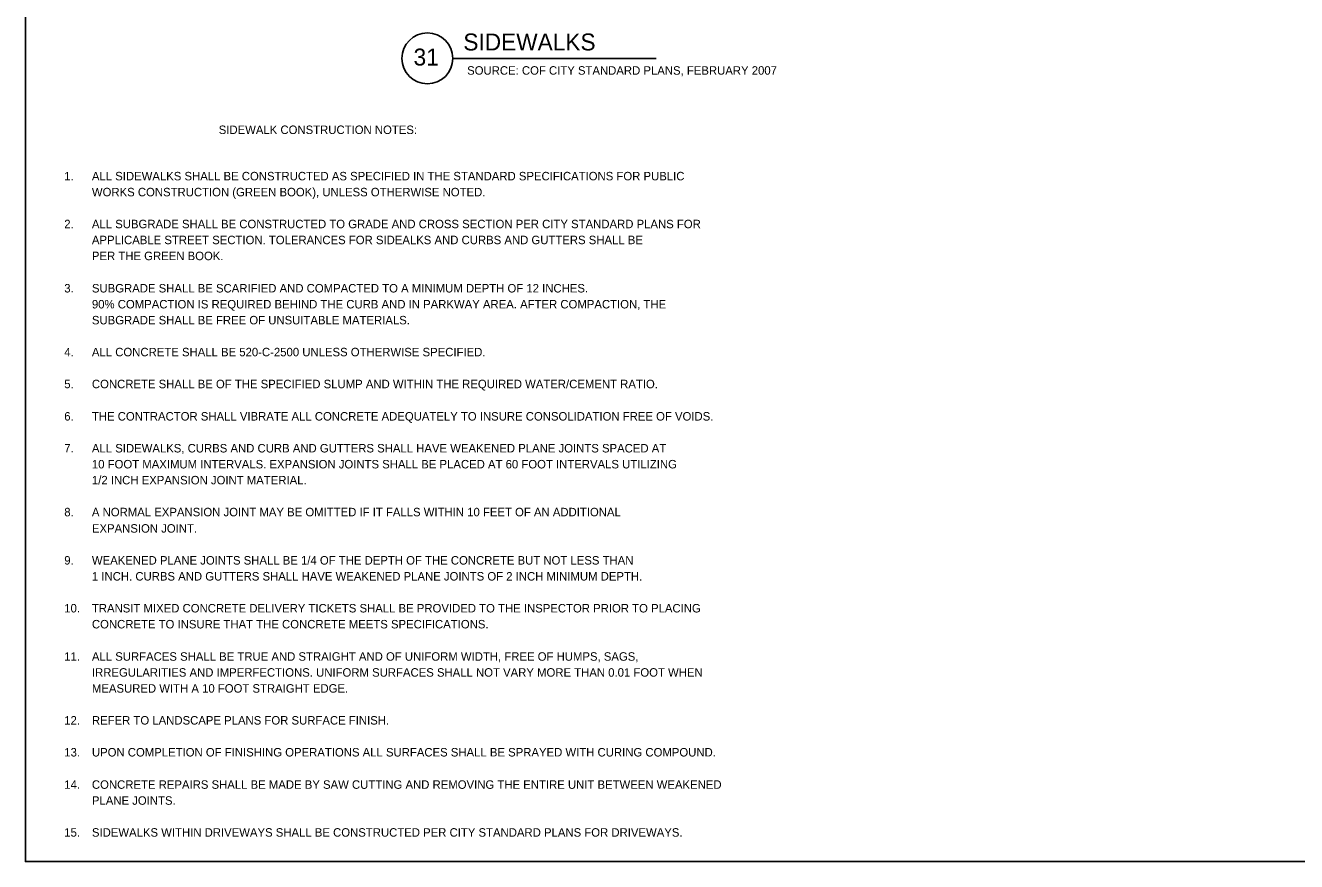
# Model space of a CAD drawing. Extents: x -118779 to -116979, y -104389 to -102939.
# Drawn here: x -118779 to -117879, y -104389 to -103797 of the extents above; entities that cross this region are included whole.
import ezdxf

# ---------------------------------------------------------------- set-up
doc = ezdxf.new("R2010")
doc.units = 0
for name, color, linetype in [('Default', 7, 'Continuous'), ('Misc CnstDet(22)', 7, 'Continuous'), ('Nongeo Data(60)', 7, 'Continuous')]:
    doc.layers.add(name, color=color, linetype=linetype)

msp = doc.modelspace()

# ---------------------------------------------------------------- linework, layer by layer
at = {"layer": 'Default'}
msp.add_lwpolyline([(-118779.39, -102939.25), (-116979.39, -102939.25), (-116979.39, -104389.25), (-118779.39, -104389.25)], close=True, dxfattribs=at)
at = {"layer": 'Nongeo Data(60)'}
msp.add_line((-118476.78, -103820.62), (-118332.78, -103820.62), dxfattribs=at)
msp.add_circle((-118494.78, -103820.62), 18, dxfattribs=at)

# ---------------------------------------------------------------- texts
at = {"layer": 'Misc CnstDet(22)'}
for s, height, p in [('SIDEWALKS', 12, (-118469.33, -103815.02)), ('31', 12, (-118504.57, -103825.69)), ('SOURCE: COF CITY STANDARD PLANS, FEBRUARY 2007', 6, (-118466.65, -103832.18)), ('SIDEWALK CONSTRUCTION NOTES:', 6, (-118642.52, -103874.18)), ('1.', 6, (-118751.88, -103906.99)), ('ALL SIDEWALKS SHALL BE CONSTRUCTED AS SPECIFIED IN THE STANDARD SPECIFICATIONS FOR PUBLIC', 6, (-118732.31, -103906.99)), ('WORKS CONSTRUCTION (GREEN BOOK), UNLESS OTHERWISE NOTED.', 6, (-118732.31, -103918.29)), ('2.', 6, (-118751.88, -103940.88)), ('ALL SUBGRADE SHALL BE CONSTRUCTED TO GRADE AND CROSS SECTION PER CITY STANDARD PLANS FOR', 6, (-118732.31, -103940.88)), ('APPLICABLE STREET SECTION. TOLERANCES FOR SIDEALKS AND CURBS AND GUTTERS SHALL BE', 6, (-118732.31, -103952.18)), ('PER THE GREEN BOOK.', 6, (-118732.31, -103963.48)), ('3.', 6, (-118751.88, -103986.36)), ('SUBGRADE SHALL BE SCARIFIED AND COMPACTED TO A MINIMUM DEPTH OF 12 INCHES.', 6, (-118732.31, -103986.36)), ('90% COMPACTION IS REQUIRED BEHIND THE CURB AND IN PARKWAY AREA. AFTER COMPACTION, THE', 6, (-118732.31, -103997.66)), ('SUBGRADE SHALL BE FREE OF UNSUITABLE MATERIALS.', 6, (-118732.31, -104008.95)), ('4.', 6, (-118751.88, -104031.55)), ('ALL CONCRETE SHALL BE 520-C-2500 UNLESS OTHERWISE SPECIFIED.', 6, (-118732.31, -104031.55)), ('5.', 6, (-118751.88, -104054.15)), ('CONCRETE SHALL BE OF THE SPECIFIED SLUMP AND WITHIN THE REQUIRED WATER/CEMENT RATIO.', 6, (-118732.31, -104054.15)), ('6.', 6, (-118751.88, -104077.03)), ('THE CONTRACTOR SHALL VIBRATE ALL CONCRETE ADEQUATELY TO INSURE CONSOLIDATION FREE OF VOIDS.', 6, (-118732.31, -104077.03)), ('7.', 6, (-118751.88, -104099.62)), ('ALL SIDEWALKS, CURBS AND CURB AND GUTTERS SHALL HAVE WEAKENED PLANE JOINTS SPACED AT', 6, (-118732.31, -104099.62)), ('10 FOOT MAXIMUM INTERVALS. EXPANSION JOINTS SHALL BE PLACED AT 60 FOOT INTERVALS UTILIZING', 6, (-118732.31, -104110.92)), ('1/2 INCH EXPANSION JOINT MATERIAL.', 6, (-118732.31, -104122.22)), ('8.', 6, (-118751.88, -104144.82)), ('A NORMAL EXPANSION JOINT MAY BE OMITTED IF IT FALLS WITHIN 10 FEET OF AN ADDITIONAL', 6, (-118732.31, -104144.82)), ('EXPANSION JOINT.', 6, (-118732.31, -104156.4)), ('9.', 6, (-118751.88, -104178.99)), ('WEAKENED PLANE JOINTS SHALL BE 1/4 OF THE DEPTH OF THE CONCRETE BUT NOT LESS THAN', 6, (-118732.31, -104178.99)), ('1 INCH. CURBS AND GUTTERS SHALL HAVE WEAKENED PLANE JOINTS OF 2 INCH MINIMUM DEPTH.', 6, (-118732.31, -104190.29)), ('10.', 6, (-118751.88, -104212.89)), ('TRANSIT MIXED CONCRETE DELIVERY TICKETS SHALL BE PROVIDED TO THE INSPECTOR PRIOR TO PLACING', 6, (-118732.31, -104212.89)), ('CONCRETE TO INSURE THAT THE CONCRETE MEETS SPECIFICATIONS.', 6, (-118732.31, -104224.19)), ('11.', 6, (-118751.88, -104247.06)), ('ALL SURFACES SHALL BE TRUE AND STRAIGHT AND OF UNIFORM WIDTH, FREE OF HUMPS, SAGS,', 6, (-118732.31, -104247.06)), ('IRREGULARITIES AND IMPERFECTIONS. UNIFORM SURFACES SHALL NOT VARY MORE THAN 0.01 FOOT WHEN', 6, (-118732.31, -104258.36)), ('MEASURED WITH A 10 FOOT STRAIGHT EDGE.', 6, (-118732.31, -104269.66)), ('12.', 6, (-118751.88, -104292.26)), ('REFER TO LANDSCAPE PLANS FOR SURFACE FINISH.', 6, (-118732.31, -104292.26)), ('13.', 6, (-118751.88, -104314.86)), ('UPON COMPLETION OF FINISHING OPERATIONS ALL SURFACES SHALL BE SPRAYED WITH CURING COMPOUND.', 6, (-118732.31, -104314.86)), ('14.', 6, (-118751.88, -104337.73)), ('CONCRETE REPAIRS SHALL BE MADE BY SAW CUTTING AND REMOVING THE ENTIRE UNIT BETWEEN WEAKENED', 6, (-118732.31, -104337.73)), ('PLANE JOINTS.', 6, (-118732.31, -104349.03)), ('15.', 6, (-118751.88, -104371.63)), ('SIDEWALKS WITHIN DRIVEWAYS SHALL BE CONSTRUCTED PER CITY STANDARD PLANS FOR DRIVEWAYS.', 6, (-118732.31, -104371.63))]:
    msp.add_text(s, height=height, dxfattribs=at).set_placement(p)

doc.saveas('drawing.dxf')
